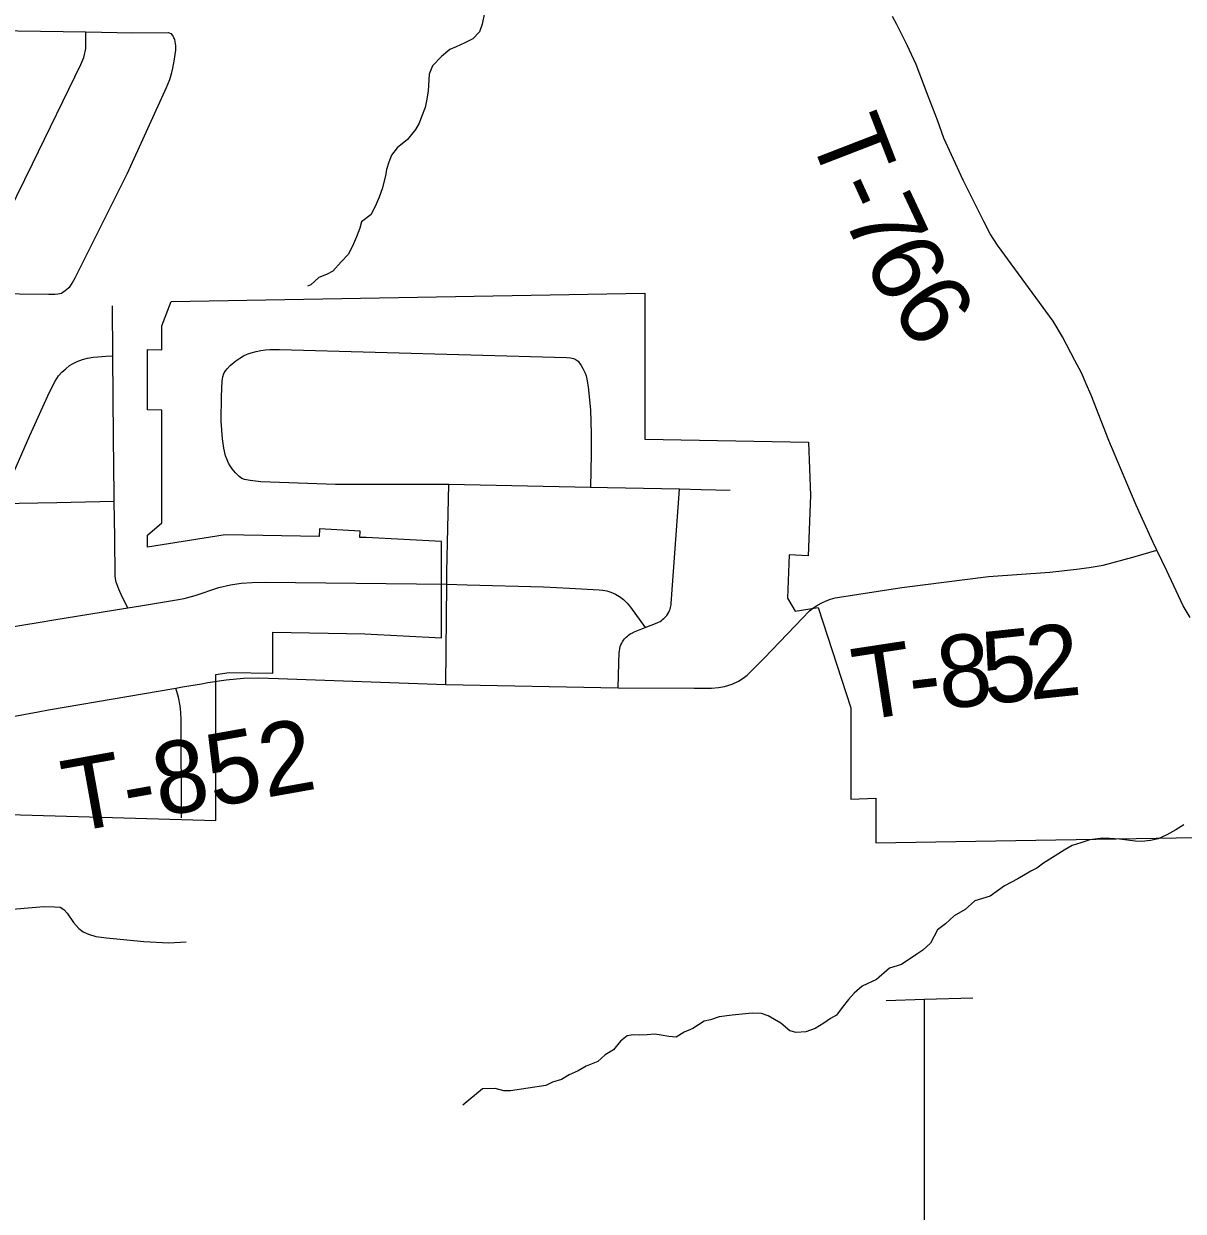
# Model space of a CAD drawing. Extents: x 0 to 34, y 0 to 22.
# Drawn here: x 6.418 to 7.33, y 17.555 to 18.489 of the extents above; entities that cross this region are included whole.
import ezdxf

# ---------------------------------------------------------------- set-up
doc = ezdxf.new("R2010")
doc.units = 0
for name, color, linetype in [('GM_X_City_Street', 7, 'Continuous'), ('GM_X_Corporation', 7, 'Continuous'), ('GM_X_Minor_River', 7, 'Continuous'), ('GM_X_Township_Road', 7, 'Continuous'), ('GM_X_Township_Road_Text', 7, 'Continuous')]:
    doc.layers.add(name, color=color, linetype=linetype)

msp = doc.modelspace()

# ---------------------------------------------------------------- linework, layer by layer
at = {"layer": 'GM_X_City_Street'}
for points in [[(6.38177, 17.7893), (6.41208, 17.79317), (6.43368, 17.79502), (6.44203, 17.79476), (6.4466, 17.79445), (6.44927, 17.7926), (6.45198, 17.7896), (6.45701, 17.78245), (6.46125, 17.77758), (6.4647, 17.77497), (6.4689, 17.77314), (6.47461, 17.77132), (6.48298, 17.77031), (6.51224, 17.76733), (6.53198, 17.76649), (6.54564, 17.76708)], [(7.09587, 17.72113), (7.12619, 17.7221), (7.16412, 17.72331)], [(7.11515, 17.34222), (7.11516, 17.34322), (7.13861, 17.34384), (7.14243, 17.34445), (7.14391, 17.34544), (7.14539, 17.34803), (7.14638, 17.35136), (7.14658, 17.36036), (7.14596, 17.41617), (7.12613, 17.53512), (7.126, 17.54233), (7.12619, 17.7221)]]:
    msp.add_lwpolyline(points, dxfattribs=at)
at = {"layer": 'GM_X_Corporation'}
msp.add_lwpolyline([(6.38806, 17.8678), (6.56883, 17.86249), (6.56883, 17.97723), (6.57949, 17.97892), (6.61377, 17.97833), (6.61377, 18.01052), (6.68592, 18.00927), (6.74625, 18.0061), (6.74625, 18.08186), (6.68705, 18.08496), (6.68213, 18.08505), (6.6823, 18.08997), (6.65034, 18.09165), (6.65013, 18.08577), (6.57628, 18.08707), (6.51511, 18.07737), (6.51511, 18.08666), (6.5264, 18.09647), (6.5264, 18.18511), (6.51504, 18.18531), (6.51504, 18.23265), (6.5264, 18.23246), (6.5264, 18.25139), (6.53374, 18.2705), (6.90614, 18.27699), (6.90614, 18.16223), (7.0349, 18.15998), (7.03637, 18.11796), (7.03472, 18.07064), (7.01959, 18.07143), (7.0184, 18.03736), (7.02436, 18.02703), (7.04251, 18.02991), (7.06808, 17.95119), (7.06808, 17.87941), (7.08777, 17.8801), (7.08777, 17.84487), (7.38675, 17.85009)], dxfattribs=at)
at = {"layer": 'GM_X_Minor_River'}
for points in [[(6.78002, 18.49716), (6.77831, 18.48837), (6.77617, 18.48224), (6.77098, 18.4768), (6.76461, 18.47362), (6.75785, 18.47043), (6.75297, 18.46842), (6.74627, 18.46295), (6.73922, 18.45557), (6.73671, 18.44905), (6.73585, 18.43571), (6.73449, 18.42808), (6.73347, 18.42273), (6.73059, 18.41544), (6.7288, 18.41046), (6.72587, 18.40545), (6.71959, 18.39771), (6.7114, 18.39106), (6.70698, 18.38526), (6.70481, 18.37989), (6.70304, 18.37414), (6.70238, 18.36918), (6.69957, 18.35885), (6.69743, 18.35234), (6.69489, 18.34696), (6.69089, 18.33889), (6.68344, 18.33302), (6.68203, 18.32804), (6.67952, 18.32114), (6.67626, 18.31384), (6.67299, 18.30731), (6.66743, 18.30148), (6.66076, 18.29411), (6.65589, 18.29172), (6.64988, 18.28931), (6.64356, 18.28346), (6.64101, 18.28234)], [(7.33003, 17.85923), (7.32368, 17.85529), (7.31656, 17.85133), (7.30981, 17.84814), (7.30377, 17.84686), (7.29697, 17.84595), (7.29166, 17.84621), (7.27951, 17.84785), (7.27154, 17.84844), (7.26623, 17.8487), (7.25603, 17.84733), (7.24889, 17.84489), (7.24211, 17.84284), (7.23575, 17.83928), (7.21967, 17.82904), (7.21445, 17.82512), (7.20958, 17.82273), (7.19947, 17.81681), (7.18898, 17.81125), (7.17779, 17.80302), (7.16574, 17.79933), (7.15792, 17.79269), (7.14932, 17.78756), (7.14263, 17.78133), (7.13629, 17.77663), (7.13082, 17.76624), (7.12487, 17.76078), (7.12002, 17.75763), (7.10807, 17.74938), (7.09866, 17.74651), (7.08824, 17.73754), (7.07698, 17.73235), (7.07065, 17.72689), (7.06621, 17.72184), (7.06142, 17.71565), (7.057, 17.70947), (7.05212, 17.70708), (7.0469, 17.70316), (7.04017, 17.69921), (7.03265, 17.69639), (7.02509, 17.69584), (7.02013, 17.69725), (7.01319, 17.70319), (7.00322, 17.70905), (6.99788, 17.71084), (6.99068, 17.71106), (6.9748, 17.70957), (6.9646, 17.70821), (6.95783, 17.70578), (6.95293, 17.70491), (6.94396, 17.69901), (6.9372, 17.6962), (6.93084, 17.69225), (6.92515, 17.69289), (6.91906, 17.6939), (6.91413, 17.69455), (6.90808, 17.69404), (6.90202, 17.6939), (6.89709, 17.69418), (6.89218, 17.69331), (6.88697, 17.68901), (6.88142, 17.68243), (6.87507, 17.67848), (6.86912, 17.67303), (6.86011, 17.66941), (6.85374, 17.66585), (6.84661, 17.66265), (6.84062, 17.65909), (6.83347, 17.65704), (6.82822, 17.65426), (6.80066, 17.65023), (6.79536, 17.65012), (6.7885, 17.65187), (6.77866, 17.65165), (6.76302, 17.63876)]]:
    msp.add_lwpolyline(points, dxfattribs=at)
at = {"layer": 'GM_X_Township_Road'}
for p, q in [((6.75064, 18.05802), (6.75219, 18.12653)), ((6.97332, 18.12189), (6.95046, 18.12247)), ((6.75041, 18.04823), (6.75064, 18.05802)), ((6.74968, 17.96949), (6.75041, 18.04823)), ((6.88509, 17.96691), (6.88577, 17.98606))]:
    msp.add_line(p, q, dxfattribs=at)
for points in [[(7.33485, 18.02198), (7.32941, 18.03136), (7.31649, 18.05884), (7.30884, 18.07493), (7.30593, 18.08104), (7.29614, 18.10213), (7.29261, 18.11041), (7.28791, 18.12095), (7.27101, 18.16126), (7.25722, 18.19669), (7.2533, 18.20573), (7.24938, 18.21438), (7.2443, 18.22416), (7.23456, 18.24259), (7.22718, 18.25498), (7.18349, 18.31457), (7.1777, 18.32369), (7.1726, 18.33336), (7.15659, 18.36571), (7.1472, 18.38566), (7.14132, 18.39884), (7.13619, 18.41279), (7.12908, 18.43164), (7.11961, 18.45652), (7.11256, 18.47195), (7.10437, 18.48813), (7.1009, 18.49433)], [(6.36601, 18.48436), (6.41325, 18.48317), (6.46664, 18.48225), (6.50374, 18.48163), (6.53137, 18.4817), (6.53233, 18.48159), (6.5334, 18.48102), (6.53459, 18.47978), (6.53535, 18.47872), (6.53598, 18.4776)], [(6.37529, 18.27808), (6.42469, 18.37866), (6.46286, 18.45667), (6.46502, 18.46218), (6.46571, 18.46441), (6.46626, 18.46658), (6.46665, 18.46923), (6.4668, 18.47154), (6.46664, 18.48225)], [(6.45045, 18.27894), (6.45304, 18.28102), (6.45398, 18.28194), (6.45473, 18.28281), (6.45603, 18.28473), (6.45825, 18.28893), (6.49938, 18.37117), (6.53014, 18.43844), (6.53269, 18.44493), (6.53425, 18.45024), (6.53509, 18.45388), (6.53637, 18.46084), (6.5372, 18.46625), (6.53742, 18.46775), (6.53748, 18.4685), (6.5375, 18.46931), (6.53745, 18.4706), (6.53738, 18.47136), (6.53718, 18.47307), (6.53692, 18.47466), (6.53653, 18.47621), (6.53629, 18.47692), (6.53598, 18.4776)], [(6.26663, 18.28082), (6.37058, 18.27915), (6.37257, 18.27898), (6.37529, 18.27808), (6.37745, 18.27718), (6.3788, 18.27682), (6.38008, 18.27665), (6.41455, 18.2763), (6.43724, 18.27607), (6.44241, 18.2762), (6.4447, 18.27634), (6.44632, 18.2766), (6.44752, 18.27706), (6.44861, 18.27769), (6.45045, 18.27894)], [(6.49975, 18.02974), (6.49535, 18.0384), (6.49276, 18.04423), (6.4906, 18.04984), (6.48985, 18.05428), (6.48938, 18.085), (6.48894, 18.11343), (6.48887, 18.11799), (6.48856, 18.1635), (6.48804, 18.22759), (6.48772, 18.26704)], [(6.39927, 18.11158), (6.42267, 18.16507), (6.43805, 18.19908), (6.44245, 18.20788), (6.44523, 18.21186), (6.44788, 18.21477), (6.45092, 18.21755), (6.45396, 18.21999), (6.45681, 18.22177), (6.46, 18.22334), (6.46415, 18.22481), (6.46792, 18.22575), (6.47255, 18.22665), (6.47623, 18.22702), (6.4824, 18.22744), (6.48804, 18.22759)], [(6.75219, 18.12653), (6.66286, 18.12655), (6.60416, 18.12861), (6.59582, 18.12962), (6.5915, 18.13062), (6.5894, 18.1314), (6.58734, 18.1328), (6.58443, 18.13567), (6.58167, 18.13886), (6.58017, 18.14117), (6.57895, 18.14337), (6.57775, 18.14597), (6.5766, 18.14902), (6.57524, 18.15515), (6.57416, 18.1624), (6.57315, 18.17627), (6.57323, 18.19562), (6.57387, 18.20804), (6.57438, 18.21119), (6.57523, 18.21386), (6.57655, 18.21597), (6.57784, 18.21755), (6.58005, 18.22001), (6.58453, 18.22388), (6.58778, 18.22598), (6.59075, 18.22764), (6.59357, 18.22898), (6.59655, 18.23014), (6.60049, 18.23118), (6.60417, 18.23185), (6.60803, 18.23238), (6.61127, 18.23266), (6.61491, 18.23272), (6.6189, 18.23255), (6.84454, 18.22627), (6.84778, 18.22608), (6.84914, 18.2259), (6.85023, 18.2256), (6.85132, 18.22514), (6.85215, 18.22464), (6.85301, 18.22399), (6.85367, 18.22339), (6.85494, 18.22196), (6.85624, 18.22001), (6.85754, 18.21776), (6.85918, 18.21416), (6.85994, 18.21198), (6.8606, 18.20934), (6.86155, 18.20341), (6.86334, 18.18523), (6.86401, 18.16665), (6.86387, 18.15072), (6.86343, 18.12435)], [(6.87696, 18.12407), (6.86343, 18.12435), (6.75219, 18.12653)], [(6.95046, 18.12247), (6.93332, 18.1229), (6.87696, 18.12407)], [(6.90655, 18.01414), (6.91577, 18.01786), (6.91703, 18.01842), (6.91816, 18.01904), (6.91923, 18.01971), (6.92015, 18.02038), (6.92118, 18.02126), (6.92214, 18.02221), (6.92276, 18.02291), (6.92337, 18.02366), (6.92426, 18.02495), (6.92496, 18.02616), (6.92559, 18.02748), (6.926, 18.02854), (6.92643, 18.02991), (6.92668, 18.03097), (6.92687, 18.03213), (6.92698, 18.0331), (6.93332, 18.1229)], [(6.32973, 18.01497), (6.32761, 18.06944), (6.32799, 18.07569), (6.32855, 18.07871), (6.32932, 18.08161), (6.33116, 18.08476), (6.33339, 18.08736), (6.34235, 18.09548), (6.35319, 18.10476), (6.35694, 18.1071), (6.36015, 18.10867), (6.36333, 18.10986), (6.36564, 18.11043), (6.36773, 18.1108), (6.37164, 18.11113), (6.39927, 18.11158), (6.44392, 18.11232), (6.48894, 18.11343)], [(7.04114, 18.03129), (7.04186, 18.03179), (7.04524, 18.0337), (7.04882, 18.0353), (7.05227, 18.03644), (7.05579, 18.0374), (7.10819, 18.04567), (7.1765, 18.05424), (7.22453, 18.05769), (7.24569, 18.05994), (7.25551, 18.06124), (7.26646, 18.06332), (7.28983, 18.0694), (7.30884, 18.07493)], [(6.50963, 18.03135), (6.53631, 18.0357), (6.54411, 18.03706), (6.55253, 18.03939), (6.57136, 18.04576), (6.58038, 18.04766), (6.58877, 18.04896), (6.59742, 18.04961), (6.60764, 18.04978), (6.75041, 18.04823), (6.76645, 18.0478)], [(6.76645, 18.0478), (6.82659, 18.04618), (6.84685, 18.0451)], [(6.84685, 18.0451), (6.87036, 18.04386), (6.87316, 18.04354), (6.8762, 18.04292), (6.87958, 18.04186), (6.883, 18.04036), (6.88624, 18.03848), (6.88941, 18.03612), (6.89234, 18.03333), (6.89486, 18.03026), (6.90655, 18.01414)], [(6.43989, 18.01997), (6.49975, 18.02974), (6.50963, 18.03135)], [(6.55767, 17.97005), (6.56267, 17.97089), (6.57696, 17.97307), (6.59062, 17.97439), (6.60273, 17.97459), (6.61788, 17.97408), (6.74968, 17.96949), (6.88509, 17.96691), (6.94505, 17.96658), (6.95867, 17.96642), (6.96417, 17.96695), (6.96888, 17.96774), (6.97479, 17.96964), (6.97979, 17.97209), (6.98346, 17.9743), (6.98653, 17.97675), (7.00032, 17.99025), (7.03013, 18.02147), (7.03572, 18.02726), (7.03898, 18.0298), (7.04114, 18.03129)], [(6.32973, 18.01497), (6.34414, 18.01479), (6.3768, 18.01338), (6.39144, 18.0126), (6.40189, 18.01377), (6.43091, 18.0185), (6.43989, 18.01997)], [(6.88577, 17.98606), (6.88608, 17.99467), (6.88619, 17.99595), (6.88644, 17.99747), (6.8869, 17.99917), (6.88739, 18.00053), (6.888, 18.00186), (6.88861, 18.00298), (6.8894, 18.00417), (6.89022, 18.00524), (6.89089, 18.006), (6.89161, 18.00673), (6.89251, 18.00753), (6.89324, 18.00811), (6.89437, 18.0089), (6.89527, 18.00944), (6.89636, 18.01), (6.89732, 18.01042), (6.90655, 18.01414)], [(6.43732, 17.94944), (6.53757, 17.96665), (6.54266, 17.96753), (6.55767, 17.97005)], [(6.54196, 17.86473), (6.54155, 17.94134), (6.54145, 17.94779), (6.54092, 17.95257), (6.53947, 17.95954), (6.53757, 17.96665)], [(6.37782, 17.93854), (6.4293, 17.94806), (6.43732, 17.94944)]]:
    msp.add_lwpolyline(points, dxfattribs=at)

# ---------------------------------------------------------------- texts
at = {"layer": 'GM_X_Township_Road_Text'}
for s, height, rotation, p in [('T', 0.05682, 291.15198, (7.03474, 18.40235)), ('-', 0.05682, 294.54794, (7.0515, 18.35933)), ('7', 0.05682, 295.09933, (7.06144, 18.33756)), ('6', 0.05682, 297.58597, (7.07748, 18.30346)), ('6', 0.05682, 305.7416, (7.09831, 18.26494)), ('5', 0.05682, 6.03733, (7.17403, 17.95363)), ('2', 0.05682, 5.98503, (7.20882, 17.95731)), ('T', 0.05682, 8.68588, (7.07474, 17.94075)), ('8', 0.05682, 6.26778, (7.1393, 17.94981)), ('-', 0.05682, 6.70482, (7.11624, 17.9471)), ('T-852', 0.056818, 10.15783, (6.45444, 17.8528))]:
    msp.add_text(s, height=height, rotation=rotation, dxfattribs=at).set_placement(p)

doc.saveas('drawing.dxf')
